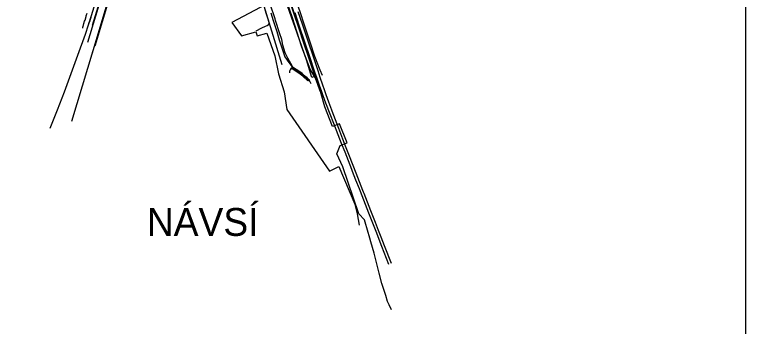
# Model space of a CAD drawing. Extents: x -440566 to -438466, y -1132677 to -1129707.
# Drawn here: x -439779 to -438466, y -1131383 to -1130824 of the extents above; entities that cross this region are included whole.
import ezdxf

# ---------------------------------------------------------------- set-up
doc = ezdxf.new("R2010")
doc.units = 0
for name, color, linetype in [('Vrstva 1', 7, 'Continuous'), ('Vrstva 11', 7, 'Continuous'), ('Vrstva 20', 7, 'Continuous'), ('Vrstva 23', 7, 'Continuous'), ('Vrstva 34', 7, 'Continuous'), ('Vrstva 4', 7, 'Continuous'), ('Vrstva 52', 7, 'Continuous'), ('Vrstva 57', 7, 'Continuous'), ('Vrstva 59', 7, 'Continuous'), ('Vrstva 63', 7, 'Continuous'), ('Vrstva 9', 7, 'Continuous')]:
    doc.layers.add(name, color=color, linetype=linetype)

msp = doc.modelspace()

# ---------------------------------------------------------------- linework, layer by layer
at = {"layer": 'Vrstva 1'}
msp.add_lwpolyline([(-440566, -1129707), (-438466, -1129707), (-438466, -1132677), (-440566, -1132677)], close=True, dxfattribs=at)
at = {"layer": 'Vrstva 11'}
for points in [[(-439344.8, -1130853), (-439334.8, -1130847.6), (-439327.9, -1130844.9), (-439325.1, -1130843.5), (-439322.8, -1130841.9), (-439321.7, -1130839.2), (-439322.2, -1130835.8), (-439326.6, -1130821.6), (-439331.2, -1130806.3), (-439334.8, -1130794.6), (-439341.6, -1130772.2), (-439347.4, -1130754.1), (-439353.2, -1130735.4), (-439356.7, -1130724.1), (-439358.9, -1130721.3), (-439364.2, -1130721.5)], [(-439318.3, -1130821), (-439314, -1130834.6), (-439307.9, -1130854.4), (-439303.3, -1130869.1), (-439295.3, -1130894.6), (-439293.3, -1130899.6), (-439286.2, -1130910), (-439280.7, -1130917.1), (-439271.1, -1130924.9), (-439263.4, -1130929.4), (-439258.8, -1130933.6), (-439248.7, -1130941.2), (-439252, -1130942.7), (-439261.2, -1130934.6), (-439266, -1130931), (-439272.7, -1130926.3), (-439282, -1130920.1), (-439283.5, -1130922.8), (-439285.1, -1130925.3), (-439284.7, -1130928.6)]]:
    msp.add_lwpolyline(points, dxfattribs=at)
at = {"layer": 'Vrstva 20'}
for points in [[(-439714.5, -1131027.8), (-439701.8, -1130995), (-439689.2, -1130962.4), (-439677, -1130929.7), (-439665, -1130896.9), (-439651.6, -1130859), (-439640.8, -1130825.8), (-439630.6, -1130792.3)], [(-439106.2, -1131272.4), (-439118.8, -1131240.1), (-439129.4, -1131213), (-439142.3, -1131179.9), (-439151.4, -1131156.8), (-439157.4, -1131141.3), (-439159.4, -1131136.3), (-439165.5, -1131120.8), (-439171.5, -1131105.3), (-439172.3, -1131103.4), (-439173, -1131101.5), (-439179.1, -1131086.1), (-439185.1, -1131070.6), (-439191.2, -1131055.1), (-439197.2, -1131039.7), (-439205.3, -1131019.1), (-439211.8, -1131002.5), (-439219.4, -1130982.8), (-439224.2, -1130969.9), (-439227.7, -1130960.4), (-439230.5, -1130952.7), (-439235.4, -1130938.7), (-439239.4, -1130927.3), (-439248.6, -1130899.9), (-439256.8, -1130875.4), (-439267.4, -1130843.3), (-439275, -1130820.6)], [(-439101.7, -1131270.5), (-439114.2, -1131238.4), (-439120.3, -1131223), (-439125, -1131211), (-439130.5, -1131197), (-439138.7, -1131176), (-439144.8, -1131160.5), (-439150.8, -1131145), (-439151.9, -1131142.2), (-439153, -1131139.4), (-439159.1, -1131123.9), (-439165.2, -1131108.4), (-439177.1, -1131077.8), (-439184.1, -1131060), (-439189, -1131047.4), (-439192.7, -1131037.9), (-439196.5, -1131028.3), (-439202.5, -1131012.9), (-439208.3, -1130997.3), (-439209.1, -1130995.4), (-439214.4, -1130980.9), (-439219.1, -1130967.9), (-439222.3, -1130958.6), (-439225, -1130950.7), (-439229.7, -1130936.8), (-439233.5, -1130925.1), (-439242.4, -1130897.9), (-439250.6, -1130873.2), (-439261.5, -1130841), (-439269.2, -1130818.8)]]:
    msp.add_lwpolyline(points, dxfattribs=at)
at = {"layer": 'Vrstva 23'}
msp.add_line((-439607.7, -1130788.1), (-439639.1, -1130892.9), dxfattribs=at)
at = {"layer": 'Vrstva 34'}
msp.add_line((-439297.8, -1130914.3), (-439362.8, -1130701.8), dxfattribs=at)
at = {"layer": 'Vrstva 4'}
for points in [[(-439237.7, -1130937.7), (-439242, -1130926.7), (-439250.2, -1130901.7), (-439259, -1130875.5), (-439267.6, -1130849.5), (-439276.9, -1130821.5), (-439290.2, -1130781.7), (-439298.8, -1130756), (-439310.5, -1130722.6), (-439322.9, -1130685.2)], [(-439237.7, -1130937.7), (-439241, -1130926.5), (-439249.7, -1130901.2), (-439258.4, -1130875), (-439266.8, -1130849.3), (-439276.3, -1130820.7), (-439289.3, -1130782.2), (-439298.3, -1130755.5), (-439310, -1130722), (-439322.4, -1130684.9)]]:
    msp.add_lwpolyline(points, dxfattribs=at)
at = {"layer": 'Vrstva 52'}
for p, q in [((-439570, -1130615.4), (-439647.6, -1130874)), ((-439570.7, -1130615.2), (-439639.2, -1130843.5)), ((-439596.8, -1130755.1), (-439634.3, -1130880.3)), ((-439604.1, -1130774.5), (-439676.4, -1131015.5)), ((-439310.6, -1130831.4), (-439319.5, -1130805.4)), ((-439309.8, -1130834.4), (-439310.6, -1130831.4)), ((-439302.3, -1130858.5), (-439309.8, -1130834.4)), ((-439298.9, -1130868.9), (-439302.3, -1130858.5)), ((-439296.7, -1130878.8), (-439298.9, -1130868.9)), ((-439292.4, -1130892.3), (-439296.7, -1130878.8)), ((-439290.3, -1130897.1), (-439292.4, -1130892.3)), ((-439289.5, -1130898.6), (-439290.3, -1130897.1)), ((-439287.6, -1130902.3), (-439289.5, -1130898.6)), ((-439279.6, -1130916.9), (-439287.6, -1130902.3)), ((-439277.6, -1130919.4), (-439279.6, -1130916.9)), ((-439268.2, -1130925.6), (-439277.6, -1130919.4)), ((-439262.2, -1130929.7), (-439268.2, -1130925.6)), ((-439255.3, -1130935.4), (-439262.2, -1130929.7)), ((-439253.2, -1130937.5), (-439255.3, -1130935.4)), ((-439248.3, -1130943.5), (-439253.2, -1130937.5)), ((-439245.8, -1130948), (-439248.3, -1130943.5))]:
    msp.add_line(p, q, dxfattribs=at)
for points in [[(-439656.3, -1130848.1), (-439655.9, -1130846.1), (-439655.7, -1130845.2), (-439654.2, -1130839.9), (-439652.9, -1130835.7), (-439652.2, -1130833.7), (-439650.3, -1130827.5), (-439649.9, -1130826.2), (-439648.3, -1130821.3)], [(-439647.7, -1130847.9), (-439646.2, -1130842.5), (-439644.5, -1130838.4), (-439643.7, -1130836.4), (-439641.8, -1130830.2), (-439641.4, -1130828.8), (-439639.9, -1130823.9)]]:
    msp.add_lwpolyline(points, dxfattribs=at)
at = {"layer": 'Vrstva 57'}
for p, q in [((-439317.4, -1130800.5), (-439388.4, -1130838.3)), ((-439388.4, -1130838.3), (-439371.2, -1130861.9)), ((-439371.2, -1130861.9), (-439345.5, -1130854.7)), ((-439345.5, -1130854.7), (-439342.9, -1130862.1)), ((-439342.9, -1130862.1), (-439325.6, -1130857)), ((-439325.6, -1130857), (-439311.1, -1130898)), ((-439311.1, -1130898), (-439304.4, -1130930.4)), ((-439304.4, -1130930.4), (-439294.3, -1130962.3)), ((-439294.3, -1130962.3), (-439289.7, -1130994.4)), ((-439289.7, -1130994.4), (-439213, -1131104.9)), ((-439213, -1131104.9), (-439196, -1131096.5)), ((-439196, -1131096.5), (-439167.8, -1131163.7)), ((-439167.8, -1131163.7), (-439163.6, -1131181.3)), ((-439163.6, -1131181.3), (-439159.6, -1131201.6))]:
    msp.add_line(p, q, dxfattribs=at)
at = {"layer": 'Vrstva 59'}
msp.add_lwpolyline([(-439240.6, -1130935.1), (-439245, -1130936.6), (-439254.5, -1130905.2), (-439274.8, -1130847.1), (-439298, -1130780.8), (-439307.8, -1130753), (-439314.4, -1130732.2), (-439325.8, -1130696.2), (-439342.9, -1130644.2), (-439353.4, -1130615.7)], dxfattribs=at)
at = {"layer": 'Vrstva 63'}
for points in [[(-439229.7, -1130961.1), (-439234.3, -1130947.5), (-439238.5, -1130936.8), (-439247.9, -1130921.6), (-439263.3, -1130880.5), (-439279.5, -1130829.6), (-439292.6, -1130791.4), (-439307.6, -1130752.9), (-439315.7, -1130727.4), (-439322.7, -1130704.6), (-439333.3, -1130672.3), (-439337.2, -1130661.2)], [(-439101.5, -1131353.3), (-439105.7, -1131344.5), (-439108.9, -1131338.2), (-439112, -1131327.7), (-439119, -1131306.4), (-439124, -1131287.5), (-439128.7, -1131268.4), (-439132.8, -1131252), (-439138.6, -1131231.7), (-439140.5, -1131225), (-439148.8, -1131196.2), (-439149.9, -1131191.9), (-439160.3, -1131181.3), (-439179.3, -1131124.9), (-439188.8, -1131096.8), (-439199.6, -1131073.7), (-439193.7, -1131059), (-439181.4, -1131054.1), (-439195.1, -1131020), (-439207.7, -1131024.6), (-439221.2, -1130989.2), (-439229.4, -1130961.8), (-439235, -1130945.1), (-439238.4, -1130936.8), (-439247.5, -1130922.5), (-439263.2, -1130880.5), (-439279.5, -1130829.6), (-439292.5, -1130791.3)]]:
    msp.add_lwpolyline(points, dxfattribs=at)
at = {"layer": 'Vrstva 9'}
msp.add_lwpolyline([(-439225.7, -1130933.4), (-439229.6, -1130923.9), (-439239.1, -1130898.9), (-439247.8, -1130873.6), (-439257.6, -1130845), (-439266.6, -1130817.1), (-439278.6, -1130785.6), (-439289.8, -1130752.5), (-439300.6, -1130719.6), (-439315.2, -1130678.2)], dxfattribs=at)

# ---------------------------------------------------------------- texts
at = {"layer": 'Vrstva 1'}
msp.add_text('NÁVSÍ', height=50, dxfattribs=at).set_placement((-439541.2, -1131220.8))

doc.saveas('drawing.dxf')
